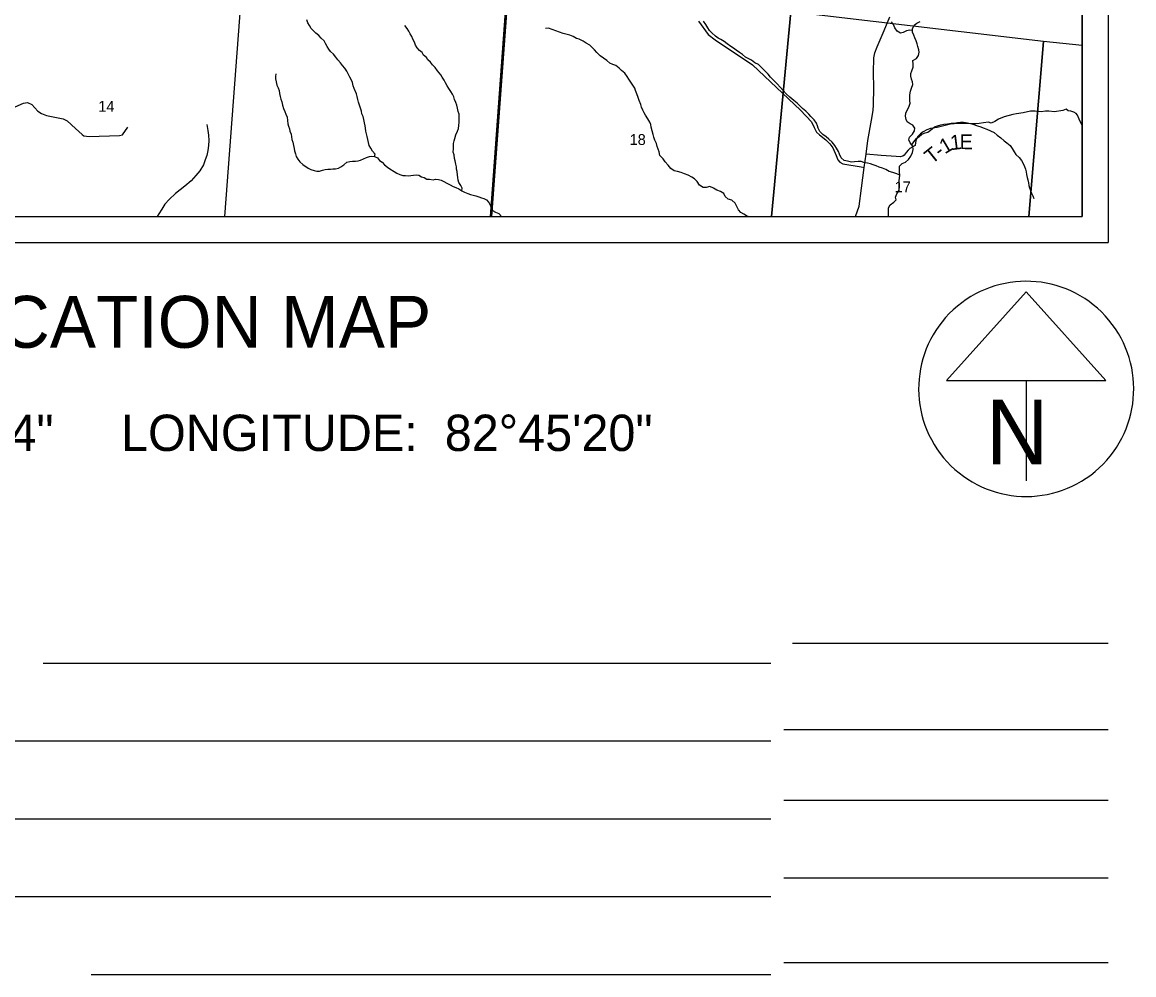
# Model space of a CAD drawing. Extents: x -13.1 to 43.1, y 0 to 22.
# Drawn here: x 4.813 to 9.099, y 11.177 to 14.849 of the extents above; entities that cross this region are included whole.
import ezdxf

# ---------------------------------------------------------------- set-up
doc = ezdxf.new("R2010")
doc.units = 0
for name, color, linetype in [('GM_X_Corporation', 7, 'Continuous'), ('GM_X_Minor_River', 7, 'Continuous'), ('GM_X_Section_Text', 7, 'Continuous'), ('GM_X_State_Route', 7, 'Continuous'), ('GM_X_Township_Road', 7, 'Continuous'), ('GM_X_Township_Road_Text', 7, 'Continuous'), ('SH_Data', 7, 'Continuous'), ('SH_Text', 7, 'Continuous')]:
    doc.layers.add(name, color=color, linetype=linetype)

msp = doc.modelspace()

# ---------------------------------------------------------------- linework, layer by layer
at = {"layer": 'GM_X_Corporation'}
for points in [[(7.0807, 20.9), (2.1, 20.9), (2.1, 14.1), (6.6193, 14.1), (6.6994, 15.2069), (6.7531, 15.956), (6.8236, 16.9075), (6.9509, 19.0179), (7.0108, 19.8446), (7.0164, 19.8954), (7.0617, 20.6133)], [(7.0804, 20.9), (2.1, 20.9), (2.1, 14.1), (6.619, 14.1), (6.6992, 15.2074), (6.7528, 15.9566), (6.8234, 16.908), (6.8365, 17.1257), (6.9507, 19.0184), (6.9616, 19.1692), (7.0106, 19.8452), (7.0162, 19.896), (7.0615, 20.6138)], [(2.1, 17.2152), (2.1, 14.1), (6.619, 14.1), (6.6992, 15.2074), (6.7528, 15.9566), (6.8234, 16.908), (4.4304, 17.0575), (3.8328, 17.0966), (2.8442, 17.1637), (2.1437, 17.2135)], [(6.619, 14.1), (8.9, 14.1), (8.9, 15.7487), (8.7782, 15.7572), (7.8612, 15.855), (6.7528, 15.9566), (6.6992, 15.2074)], [(6.619, 14.1), (8.9, 14.1), (8.9, 15.7487), (8.7782, 15.7572), (7.8612, 15.855), (6.7528, 15.9566), (6.6992, 15.2074)], [(6.6193, 14.1), (8.9, 14.1), (8.9, 15.7481), (8.7784, 15.7567), (7.8614, 15.8545), (6.7531, 15.956), (6.6994, 15.2069)], [(4.6107, 14.1), (5.5941, 14.1), (5.6613, 14.9873), (4.6921, 15.0289)], [(6.623, 14.1), (7.7024, 14.1), (7.7762, 14.8894), (6.6851, 14.9543)], [(7.7024, 14.1), (8.6942, 14.1), (8.7515, 14.7745), (7.7762, 14.8894)], [(8.6942, 14.1), (8.9, 14.1), (8.9, 14.7592), (8.7515, 14.7745)]]:
    msp.add_lwpolyline(points, close=True, dxfattribs=at)
at = {"layer": 'GM_X_Minor_River'}
for points in [[(6.1717, 14.3309), (6.1733, 14.3408), (6.1636, 14.3515), (6.1569, 14.3638), (6.1513, 14.3741), (6.1484, 14.3848), (6.1455, 14.3966), (6.1434, 14.4084), (6.1405, 14.419), (6.1379, 14.4289), (6.1366, 14.4404), (6.1352, 14.4499), (6.1326, 14.4613), (6.1301, 14.4739), (6.1272, 14.4849), (6.1228, 14.4956), (6.1206, 14.5055), (6.1174, 14.5181), (6.1133, 14.5291), (6.11, 14.5406), (6.1067, 14.5509), (6.1038, 14.5623), (6.1013, 14.573), (6.0932, 14.5936), (6.0895, 14.6039), (6.0859, 14.6161), (6.0815, 14.6279), (6.0766, 14.6375), (6.07, 14.6497), (6.0644, 14.6597), (6.0565, 14.6723), (6.0479, 14.6819), (6.0401, 14.6926), (6.0303, 14.7041), (6.0221, 14.7141), (6.0131, 14.7256), (6.0018, 14.736), (5.9955, 14.7456), (5.9892, 14.7556), (5.9821, 14.767), (5.9769, 14.777), (5.9656, 14.787), (5.9562, 14.7981), (5.9453, 14.8066), (5.9269, 14.8251), (5.9202, 14.8366), (5.9139, 14.8465), (5.9098, 14.8576)], [(6.5076, 14.199), (6.5096, 14.2096), (6.5036, 14.2192), (6.4969, 14.2307), (6.494, 14.2402), (6.4926, 14.2501), (6.4908, 14.2596), (6.4899, 14.2729), (6.4877, 14.2824), (6.4871, 14.2919), (6.4853, 14.3022), (6.482, 14.3144), (6.4802, 14.3239), (6.4781, 14.3372), (6.4744, 14.3483), (6.4765, 14.3608), (6.4755, 14.3714), (6.476, 14.3813), (6.4788, 14.3911), (6.4812, 14.401), (6.4855, 14.4146), (6.4914, 14.4286), (6.4957, 14.4392), (6.497, 14.4505), (6.4983, 14.4634), (6.4973, 14.4741), (6.4978, 14.4843), (6.4975, 14.4938), (6.4942, 14.5049), (6.4917, 14.5171), (6.4888, 14.5285), (6.4848, 14.5399), (6.48, 14.5514), (6.4771, 14.5617), (6.4719, 14.5716), (6.4659, 14.582), (6.4581, 14.5931), (6.4521, 14.6042), (6.4454, 14.6149), (6.4398, 14.6256), (6.4327, 14.6367), (6.4275, 14.6462), (6.414, 14.6612), (6.4047, 14.6746), (6.3949, 14.6843), (6.3875, 14.695), (6.3773, 14.7039), (6.3721, 14.7134), (6.3601, 14.7219), (6.3552, 14.7315), (6.3443, 14.7392), (6.3364, 14.7496), (6.3297, 14.7607), (6.3249, 14.7714), (6.3186, 14.7832), (6.315, 14.7943), (6.3082, 14.8039), (6.3038, 14.8138), (6.2975, 14.8249), (6.2877, 14.8356)], [(8.1966, 14.259), (8.185, 14.264), (8.1706, 14.2693), (8.1558, 14.2739), (8.143, 14.2811), (8.1305, 14.286), (8.1176, 14.2906), (8.1055, 14.2952), (8.0938, 14.2993), (8.0836, 14.3024), (8.073, 14.3054), (8.0586, 14.3085), (8.0476, 14.3115), (8.0359, 14.3115), (8.0226, 14.31), (8.0109, 14.3089), (7.9954, 14.3127), (7.9825, 14.3153), (7.9708, 14.326), (7.964, 14.3396), (7.9602, 14.3506), (7.9534, 14.3631), (7.947, 14.373), (7.9368, 14.3867), (7.9228, 14.3977), (7.9129, 14.4064), (7.9001, 14.4155), (7.8884, 14.428), (7.8819, 14.4398), (7.8793, 14.4492), (7.8759, 14.4595), (7.8664, 14.4728), (7.8543, 14.4853), (7.8456, 14.4948), (7.835, 14.5054), (7.8222, 14.516), (7.8131, 14.5255), (7.801, 14.5369), (7.7889, 14.5471), (7.7734, 14.56), (7.7594, 14.5729), (7.7469, 14.5854), (7.7363, 14.5991), (7.7238, 14.6116), (7.7121, 14.623), (7.6985, 14.637), (7.689, 14.6488), (7.6758, 14.6621), (7.6626, 14.6761), (7.6516, 14.6856), (7.638, 14.6921), (7.6251, 14.7027), (7.6122, 14.7084), (7.6024, 14.7145), (7.5903, 14.7243), (7.5793, 14.7323), (7.5665, 14.7414), (7.5555, 14.749), (7.5449, 14.7554), (7.5313, 14.7649), (7.5199, 14.774), (7.5071, 14.7824), (7.4969, 14.7873), (7.4866, 14.7953), (7.4723, 14.8078), (7.4632, 14.8173), (7.4568, 14.8268), (7.4488, 14.8401), (7.4405, 14.8526)], [(8.2464, 14.8172), (8.236, 14.8186), (8.2223, 14.8152), (8.2098, 14.8092), (8.1996, 14.8069), (8.1871, 14.8141), (8.1781, 14.827), (8.1724, 14.8399), (8.1652, 14.8501)], [(8.2427, 14.6287), (8.2393, 14.6408), (8.2393, 14.6511), (8.2438, 14.6617), (8.248, 14.6757), (8.248, 14.6867), (8.2473, 14.7007), (8.2609, 14.7087), (8.2692, 14.7208), (8.2711, 14.7329), (8.2704, 14.7424), (8.267, 14.7549), (8.2636, 14.7652), (8.2602, 14.7765), (8.2556, 14.789), (8.2515, 14.7985), (8.2466, 14.811), (8.2462, 14.8232), (8.253, 14.8372), (8.2632, 14.8451), (8.275, 14.8516)], [(7.0786, 14.6906), (7.0677, 14.7016), (7.0548, 14.7099), (7.0412, 14.7194), (7.0283, 14.7327), (7.0192, 14.7422), (7.0109, 14.7517), (7.0011, 14.7608), (6.9875, 14.768), (6.9761, 14.7752), (6.9606, 14.7832), (6.95, 14.7866), (6.9375, 14.7938), (6.9247, 14.7991), (6.8982, 14.8048), (6.8842, 14.8109), (6.8569, 14.8211), (6.8426, 14.8261), (6.8301, 14.8246)], [(7.6128, 14.1), (7.6059, 14.1026), (7.5957, 14.109), (7.5843, 14.1155), (7.5748, 14.1253), (7.568, 14.1386), (7.5616, 14.1511), (7.5488, 14.1633), (7.5355, 14.1671), (7.5234, 14.1765), (7.5189, 14.1891), (7.5056, 14.1966), (7.492, 14.202), (7.4784, 14.2092), (7.4648, 14.2153), (7.4504, 14.2115), (7.4383, 14.2115), (7.4247, 14.2213), (7.416, 14.2342), (7.4057, 14.2449), (7.3955, 14.2513), (7.3812, 14.2589), (7.3672, 14.2639), (7.3535, 14.2692), (7.3399, 14.273), (7.3267, 14.2753), (7.3146, 14.2851), (7.3036, 14.2973), (7.2926, 14.3102), (7.2839, 14.3223), (7.2718, 14.3356), (7.2688, 14.3488), (7.2658, 14.3598), (7.2616, 14.3701), (7.2582, 14.3815), (7.2526, 14.394), (7.2488, 14.4061), (7.2461, 14.416), (7.2424, 14.43), (7.2382, 14.444), (7.2363, 14.4539), (7.2329, 14.4634), (7.225, 14.4766), (7.2163, 14.4899), (7.211, 14.4998), (7.2061, 14.5096), (7.2015, 14.5214), (7.1981, 14.5316), (7.1921, 14.5476), (7.1876, 14.5582), (7.183, 14.5722), (7.1781, 14.5851), (7.1747, 14.5946), (7.1679, 14.6067), (7.1603, 14.6173), (7.1524, 14.6295), (7.1452, 14.6401), (7.1365, 14.6522), (7.124, 14.6625), (7.1142, 14.672), (7.1013, 14.6818), (7.0907, 14.686), (7.0786, 14.6906)], [(5.7902, 14.6503), (5.789, 14.64), (5.7892, 14.6301), (5.7925, 14.6191), (5.7943, 14.6065), (5.8002, 14.5962), (5.8031, 14.5852), (5.8053, 14.5737), (5.8074, 14.5631), (5.8099, 14.5524), (5.814, 14.5417), (5.8161, 14.5288), (5.8209, 14.5162), (5.8257, 14.5047), (5.8298, 14.4944), (5.8338, 14.4822), (5.8359, 14.4697), (5.8373, 14.4571), (5.8394, 14.4476), (5.8439, 14.438), (5.8453, 14.4285), (5.8493, 14.4178), (5.8511, 14.4076), (5.8529, 14.3969), (5.8562, 14.3859), (5.8591, 14.3737), (5.8616, 14.3626), (5.863, 14.3531), (5.8663, 14.3409), (5.8696, 14.3314), (5.8751, 14.3207), (5.883, 14.3107), (5.895, 14.2999), (5.9154, 14.2867), (5.926, 14.2809), (5.9381, 14.2773), (5.9487, 14.2749), (5.9593, 14.2748), (5.9704, 14.2781), (5.9807, 14.2806), (5.9913, 14.282), (6.0016, 14.2818), (6.0111, 14.284), (6.0214, 14.2839), (6.0324, 14.2864), (6.042, 14.2912), (6.0524, 14.299), (6.0643, 14.3095), (6.0757, 14.3116), (6.0867, 14.3126), (6.0981, 14.3133), (6.108, 14.3146), (6.1176, 14.3176), (6.1294, 14.3223), (6.1405, 14.3275), (6.1516, 14.3312), (6.1615, 14.3329), (6.1717, 14.3309), (6.1823, 14.3258), (6.1905, 14.3159), (6.2007, 14.3089), (6.2093, 14.2989), (6.221, 14.29), (6.2308, 14.2834), (6.247, 14.273), (6.2576, 14.2675), (6.2689, 14.2624), (6.2807, 14.2585), (6.2909, 14.2584), (6.3015, 14.2567), (6.3118, 14.2573), (6.3221, 14.2591), (6.3324, 14.2601), (6.3419, 14.2589), (6.3524, 14.253), (6.3623, 14.2499), (6.3725, 14.2444), (6.3839, 14.2439), (6.3971, 14.2418), (6.4067, 14.2443), (6.4184, 14.2419), (6.4283, 14.2395), (6.4381, 14.2345), (6.4498, 14.229), (6.4626, 14.222), (6.474, 14.2161), (6.4849, 14.2118), (6.4959, 14.206), (6.5076, 14.199), (6.5178, 14.1943), (6.5306, 14.1888), (6.5409, 14.1849), (6.5515, 14.1817), (6.5624, 14.1789), (6.5734, 14.1754), (6.5833, 14.1718), (6.5931, 14.1687), (6.6037, 14.164), (6.6121, 14.1537), (6.6172, 14.1446), (6.622, 14.1279)], [(8.1528, 14.1), (8.1531, 14.1037), (8.1535, 14.1135), (8.1531, 14.123), (8.1535, 14.1332), (8.1603, 14.1446), (8.1736, 14.1548), (8.1834, 14.1639), (8.18, 14.1738), (8.1861, 14.1867), (8.1929, 14.1988), (8.1955, 14.2117), (8.1955, 14.2246), (8.1944, 14.2375), (8.1959, 14.2485), (8.1967, 14.2583), (8.1956, 14.2716), (8.1963, 14.2815), (8.1956, 14.294), (8.2066, 14.3042), (8.2194, 14.3087), (8.23, 14.3197), (8.2399, 14.333), (8.2459, 14.3462), (8.249, 14.3587), (8.2467, 14.3713), (8.2376, 14.3842), (8.232, 14.3959), (8.235, 14.4058), (8.2456, 14.4175), (8.2539, 14.4296), (8.2554, 14.4406), (8.2471, 14.452), (8.2365, 14.4577), (8.2252, 14.4645), (8.2214, 14.474), (8.2191, 14.4865), (8.2207, 14.4979), (8.2244, 14.5078), (8.2324, 14.5218), (8.2366, 14.5362), (8.2362, 14.5457), (8.2355, 14.5586), (8.2358, 14.5692), (8.2377, 14.5832), (8.2423, 14.5949), (8.2472, 14.609), (8.2465, 14.6188), (8.2427, 14.6287)], [(5.5245, 14.454), (5.529, 14.4312), (5.5311, 14.4138), (5.5318, 14.3925), (5.5309, 14.3735), (5.5285, 14.3538), (5.5246, 14.3356), (5.5184, 14.3182), (5.5115, 14.2992), (5.4977, 14.2758), (5.4824, 14.2576), (5.4648, 14.2372), (5.4396, 14.2168), (5.422, 14.2033), (5.4044, 14.1882), (5.38, 14.1655), (5.3631, 14.1474), (5.3508, 14.1277), (5.3393, 14.1103), (5.3329, 14.1)], [(8.2436, 14.3756), (8.2509, 14.3883), (8.2611, 14.4004), (8.2713, 14.4084), (8.2819, 14.4167), (8.2952, 14.422), (8.3054, 14.4254), (8.316, 14.433), (8.3311, 14.4451), (8.3421, 14.4497), (8.3557, 14.4531), (8.3671, 14.4553), (8.3815, 14.4576), (8.3955, 14.4595), (8.4057, 14.4602), (8.4201, 14.4621), (8.4307, 14.464), (8.4424, 14.4632), (8.4579, 14.461), (8.4746, 14.4572), (8.4973, 14.4496), (8.509, 14.4458), (8.5188, 14.442), (8.5328, 14.437), (8.5472, 14.4298), (8.5605, 14.4237), (8.5722, 14.4135), (8.5862, 14.4029), (8.5994, 14.3922), (8.6093, 14.3835), (8.6225, 14.3737), (8.6304, 14.3615), (8.6384, 14.349), (8.6448, 14.3395), (8.6573, 14.3278), (8.666, 14.316), (8.6728, 14.3042), (8.6785, 14.2932), (8.6822, 14.2819), (8.6845, 14.2724), (8.686, 14.2618), (8.6879, 14.2508), (8.6909, 14.2409), (8.6928, 14.2295), (8.6947, 14.2193), (8.6974, 14.2098), (8.7011, 14.2), (8.7045, 14.1893), (8.7098, 14.1795), (8.714, 14.1692)], [(6.622, 14.1279), (6.6265, 14.1234), (6.6383, 14.1169), (6.6508, 14.1108), (6.6615, 14.1)]]:
    msp.add_lwpolyline(points, dxfattribs=at)
at = {"layer": 'GM_X_State_Route'}
msp.add_lwpolyline([(8.0264, 14.1), (8.0405, 14.1396), (8.0495, 14.2089), (8.0602, 14.2894), (8.0667, 14.34), (8.0735, 14.3929), (8.0884, 14.4713), (8.0941, 14.5089), (8.0952, 14.531), (8.0963, 14.5954), (8.0961, 14.6549), (8.0975, 14.711), (8.1007, 14.7304), (8.1103, 14.7545), (8.1369, 14.8166), (8.1591, 14.8691)], dxfattribs=at)
at = {"layer": 'GM_X_Township_Road'}
for points in [[(7.4211, 14.8528), (7.4576, 14.8021), (7.4849, 14.7809), (7.6291, 14.6847), (7.8136, 14.5097), (7.8569, 14.4654), (7.8672, 14.4425), (7.8757, 14.4249), (7.8869, 14.4141), (7.9113, 14.3952), (7.9274, 14.3805), (7.9385, 14.3652), (7.9514, 14.3354), (7.958, 14.3179), (7.9658, 14.3094), (7.9778, 14.3024), (8.0483, 14.2914), (8.0602, 14.2894)], [(4.1607, 14.4075), (4.2866, 14.4047), (4.4406, 14.3863), (4.5029, 14.384), (4.5714, 14.3866), (4.6386, 14.4163), (4.6829, 14.451), (4.7124, 14.4846), (4.7273, 14.4967), (4.8181, 14.5372), (4.8333, 14.5394), (4.85, 14.5317), (4.8731, 14.5065), (4.8871, 14.4965), (4.9057, 14.4888), (4.9703, 14.4762), (4.9859, 14.4693), (5.018, 14.4395), (5.0434, 14.4154), (5.0506, 14.4111), (5.0711, 14.408), (5.1884, 14.4126), (5.199, 14.4144), (5.2197, 14.4443)], [(8.9, 14.4501), (8.8985, 14.4528), (8.8893, 14.4753), (8.8829, 14.4905), (8.8769, 14.4969), (8.8685, 14.5017), (8.8561, 14.5053), (8.8461, 14.5073), (8.8381, 14.5141), (8.8261, 14.5085), (8.7938, 14.5038), (8.7712, 14.5057), (8.7584, 14.5057), (8.742, 14.5037), (8.7188, 14.5057), (8.7016, 14.5053), (8.6731, 14.4997), (8.6467, 14.4957), (8.6327, 14.4937), (8.5995, 14.4841), (8.5774, 14.4757), (8.5629, 14.4655), (8.5494, 14.4596), (8.539, 14.4636), (8.5198, 14.4616), (8.5026, 14.458), (8.4913, 14.4576)], [(8.4913, 14.4576), (8.4779, 14.4571), (8.4606, 14.4578), (8.4386, 14.4588), (8.4069, 14.4571), (8.3924, 14.456), (8.3417, 14.4432), (8.3159, 14.4385), (8.3012, 14.4337), (8.2877, 14.4262), (8.2774, 14.4188), (8.2672, 14.4083), (8.2606, 14.3961), (8.258, 14.3847), (8.2558, 14.3739), (8.2357, 14.3621), (8.2298, 14.3553), (8.2218, 14.3472), (8.2133, 14.3367), (8.2082, 14.333)], [(8.2082, 14.333), (8.2074, 14.3324), (8.199, 14.3302), (8.1832, 14.331), (8.1247, 14.3356), (8.0667, 14.34)]]:
    msp.add_lwpolyline(points, dxfattribs=at)
at = {"layer": 'SH_Data'}
for p, q in [((9, 21), (9, 14)), ((8.9, 20.9), (8.9, 14.1)), ((2.1, 14.1), (8.9, 14.1)), ((2, 14), (9, 14)), ((8.6845, 13.8091), (8.3769, 13.4678)), ((8.9921, 13.4678), (8.6845, 13.8091)), ((8.3769, 13.4678), (8.9921, 13.4678)), ((8.6845, 13.4678), (8.6845, 13.0811)), ((8.6845, 13.4353), (8.6845, 13.4353)), ((8.6845, 13.4353), (8.6845, 13.4353)), ((7.7827, 12.4553), (9, 12.4553)), ((7.7, 12.3767), (4.8937, 12.3767)), ((9, 12.1207), (7.75, 12.1207)), ((7.7, 12.0767), (4.3895, 12.0767)), ((9, 11.8491), (7.75, 11.8491)), ((7.7, 11.7767), (3.8854, 11.7767)), ((9, 11.5491), (7.75, 11.5491)), ((7.7, 11.4767), (3.6448, 11.4767)), ((9, 11.2223), (7.75, 11.2223)), ((7.7, 11.1767), (5.0782, 11.1767))]:
    msp.add_line(p, q, dxfattribs=at)
msp.add_arc((8.6845, 13.4353), 0.4148, 129.7798, 129.7633, dxfattribs=at)

# ---------------------------------------------------------------- texts
at = {"layer": 'GM_X_Section_Text'}
for s, p in [('14', (5.1063, 14.5038)), ('18', (7.1552, 14.3756)), ('17', (8.1772, 14.1932))]:
    msp.add_text(s, height=0.04186, rotation=0, dxfattribs=at).set_placement(p)
at = {"layer": 'GM_X_Township_Road_Text'}
for s, rotation, p in [('1', 7.2212, (8.395, 14.3553)), ('E', 359.8543, (8.4278, 14.3595)), ('T', 38.8606, (8.3209, 14.2996)), ('1', 30.5363, (8.3706, 14.3394)), ('-', 38.0112, (8.3538, 14.3262))]:
    msp.add_text(s, height=0.0568, rotation=rotation, dxfattribs=at).set_placement(p)
at = {"layer": 'SH_Data'}
msp.add_text('N', height=0.25, dxfattribs=at).set_placement((8.5292, 13.144))
at = {"layer": 'SH_Text'}
for s, height, p in [('LOCATION MAP', 0.2, (4.3691, 13.5938)), ('LATITUDE:  39°23\'04"     LONGITUDE:  82°45\'20"', 0.14, (3.071, 13.1959))]:
    msp.add_text(s, height=height, dxfattribs=at).set_placement(p)

doc.saveas('drawing.dxf')
